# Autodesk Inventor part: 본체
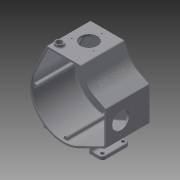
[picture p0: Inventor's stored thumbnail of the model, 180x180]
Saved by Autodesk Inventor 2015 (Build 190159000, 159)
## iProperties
Created: 2017-05
Part Number: 본체
Material: 알루미늄 6061
Document SubType Name: Modeling
Designer: mduedu
Density: 2.71 g/cm^3
Mass: 1345.72 g
Surface Area: 1824.08 cm^2
Volume: 496.576 cm^3
Appearance: 기본값
Author: mduedu
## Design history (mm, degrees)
sketch "스케치1"
  geometry: L1 (-71.801, 35.28)-(-40, 100); L2 (-40, 100)-(40, 100); L3 (40, 100)-(59.768, 59.768); L4 (59.768, 59.768)-(100, 40); L5 (100, 40)-(100, -40); L6 (100, -40)-(35.28, -71.801); A1 r 80 centre (0, 0) between (-71.801, 35.28) and (35.28, -71.801); 3 further points
  constraints: 12 end point, 4 tangent, 2 midpoint, 2 point on circle, 1 centre point, 1 coincident, 1 horizontal, 1 horizontal alignment, 1 perpendicular, 1 vertical alignment
  dimensions: "d0" = 160 diameter of A1; "d2" = 100 distance from line of L2 point (0, 0); "d3" = 100 distance from line of L5 point (0, 0); "d4" = 80 distance of L1.end L2.end; "d5" = 80 distance of L4.end L5.end
extrude "돌출1" new body sketch "스케치1" distance "d6" = 5; taper "d7" = 0 deg
fillet "모깎기1" dims "d8" = 50
sketch "스케치2"
  geometry: C1 r 22 at (0, 0); 1 further point
  constraints: 1 centre point, 1 coincident
  dimensions: "d9" = 44 diameter of C1
extrude "돌출2" join sketch "스케치2" distance "d10" = 22.5; taper "d11" = 0 deg
sketch "스케치3"
  geometry: C1 r 18.5 at (0, 0); 1 further point
  constraints: 1 centre point, 1 coincident
  dimensions: "d12" = 37 diameter of C1
extrude "돌출3" cut sketch "스케치3" distance "d13" = 9; taper "d14" = 0 deg
fillet "모깎기2" dims "d15" = 3
sketch "스케치4"
  geometry: L1 (35.28, -71.801)-(100, -40) reference; L2 (100, -40)-(100, 40) reference; L3 (100, 40)-(75.073, 52.248) reference; L4 (52.248, 75.073)-(40, 100) reference; L5 (40, 100)-(-40, 100) reference; L6 (-40, 100)-(-71.801, 35.28) reference; L7 (-36.886, 95)-(36.886, 95); L8 (36.886, 95)-(47.76, 72.868); L9 (72.868, 47.76)-(95, 36.886); L10 (95, 36.886)-(95, -36.886); L11 (95, -36.886)-(33.075, -67.313); L12 (-67.313, 33.075)-(-36.886, 95); C1 r 25 at (0, 0) reference; A1 r 50 centre (97.123, 97.123) between (52.248, 75.073) and (75.073, 52.248) reference; A2 r 80 centre (0, 0) between (-71.801, 35.28) and (35.28, -71.801) reference; A3 r 55 centre (97.123, 97.123) between (47.76, 72.868) and (72.868, 47.76); A4 r 75 centre (0, 0) between (-67.313, 33.075) and (33.075, -67.313); 1 further point
  constraints: 12 end point, 4 point on circle, 2 centre point, 7 other
  dimensions: "d16" = 5 distance between parallel lines of L7 L5
extrude "돌출4" join sketch "스케치4" distance "d17" = 100; taper "d18" = 0 deg
sketch "스케치5"
  geometry: L1 (80, 0)-(0, 0) reference; C1 r 20 at (40, -45); 2 further points
  constraints: 1 centre point, 1 midpoint, 1 vertical alignment
  dimensions: "d19" = 40 diameter of C1; "d21" = 45 distance from line of C1.centre L1
extrude "돌출5" cut sketch "스케치5" stored distance "d22" = 100; taper "d23" = 0 deg
sketch "스케치6"
  geometry: L1 (0, 0)-(0, -105) reference; L2 (80, -105)-(0, -105) reference; C1 r 9 at (14, -89); 1 further point
  constraints: 1 centre point
  dimensions: "d24" = 18 diameter of C1; "d26" = 14 distance from line of C1.centre L1; "d27" = 16 distance from line of C1.centre L2
extrude "돌출6" join sketch "스케치6" distance "d28" = 7; taper "d29" = 0 deg
hole "구멍1" diameter "d32" = 14; stored, may be unused: countersink angle "d36" = 90 deg, drill point angle "d38" = 118 deg; dims "d33" = 6, "d34" = 4, "d35" = 2, "d37" = 8, "d39" = 10, "d40" = 10
sketch "스케치7"
  geometry: L1 (-105, 0)-(-105, 80) reference; L2 (0, 0)-(0, 80) reference; C1 r 20 at (-70, 40); 2 further points
  constraints: 1 centre point, 1 horizontal alignment, 1 midpoint
  dimensions: "d41" = 40 diameter of C1; "d42" = 35 distance from line of C1.centre L1
extrude "돌출7" cut sketch "스케치7" stored distance "d43" = 7; taper "d44" = 0 deg
node "작업 평면1"
sketch "스케치8"
  geometry: L1 (47.76, 72.868)-(36.886, 95) reference; L2 (36.886, 95)-(-36.886, 95) reference; L3 (-36.886, 95)-(-67.313, 33.075) reference; L4 (33.075, -67.313)-(95, -36.886) reference; L5 (95, -36.886)-(95, 36.886) reference; L6 (95, 36.886)-(72.868, 47.76) reference; L7 (95, 36.886)-(95, -36.886) reference; L8 (-36.886, 95)-(36.886, 95) reference; L9 (36.886, 95)-(47.76, 72.868) reference; L10 (-71, 4)-(-74.893, 4); L11 (-71, -4)-(-74.893, -4); L12 (-4, -71)-(-4, -74.893); L13 (4, -71)-(4, -74.893); L14 (30.394, 91)-(30.394, 95); L15 (34.394, 87)-(40.817, 87); L16 (30.394, 95)-(36.886, 95); L17 (36.886, 95)-(37.984, 92.764); L18 (91, 30.394)-(95, 30.394); L19 (87, 34.394)-(87, 40.817); L20 (87, 40.817)-(95, 36.886); L21 (95, 36.886)-(95, 30.394); C1 r 25 at (0, 0) reference; A1 r 75 centre (0, 0) between (-67.313, 33.075) and (33.075, -67.313) reference; A2 r 55 centre (97.123, 97.123) between (47.76, 72.868) and (72.868, 47.76) reference; A3 r 4 centre (-71, 0) between (-71, 4) and (-71, -4); A4 r 4 centre (0, -71) between (-4, -71) and (4, -71); A5 r 4 centre (34.394, 91) between (30.394, 91) and (34.394, 87); A6 r 75 centre (0, 0) between (-67.313, 33.075) and (33.075, -67.313) reference; A7 r 4 centre (91, 34.394) between (91, 30.394) and (87, 34.394); 1 further point
  constraints: 24 end point, 17 point on circle, 14 tangent, 5 point on line, 4 centre point, 3 equal radius, 3 perpendicular, 3 vertical, 2 collinear, 2 horizontal, 1 horizontal alignment, 1 parallel, 1 vertical alignment
  dimensions: "d46" = 8 diameter of A3
extrude "돌출8" join sketch "스케치8" stored distance "d49" = 7; taper "d50" = 0 deg
node "작업 평면2"
sketch "스케치9"
  geometry: L1 (71.801, 0)-(71.801, 105) reference; L2 (71.801, 0)-(-35.28, 0) reference; L3 (-35.28, 0)-(-35.28, 105) reference; L4 (71.801, 105)-(-35.28, 105) reference; L5 (40, 0)-(40, 105) reference; L6 (71.801, 52.5)-(-35.28, 52.5); L7 (71.801, 20)-(40, 20); L8 (40, 20)-(40, 85); L9 (40, 85)-(71.801, 85); L10 (71.801, 85)-(71.801, 20); 1 further point
  constraints: 10 end point, 2 midpoint, 2 parallel, 2 point on line, 1 horizontal, 1 perpendicular, 1 other
  dimensions: "d52" = 20 distance between parallel lines of L7 L2
extrude "돌출9" join sketch "스케치9" distance "d53" = 8; taper "d54" = 0 deg
fillet "모깎기3" dims "d55" = 8
sketch "스케치10"
  geometry: C1 r 4 at (-63.801, -28); C2 r 4 at (-63.801, -77); A1 r 8 centre (-63.801, -28) between (-63.801, -20) and (-71.801, -28) reference; A2 r 8 centre (-63.801, -77) between (-71.801, -77) and (-63.801, -85) reference; 1 further point
  constraints: 2 centre point, 2 coincident, 1 equal radius
  dimensions: "d56" = 8 diameter of C1
extrude "돌출10" cut sketch "스케치10" stored distance "d57" = 50.5; taper "d58" = 0 deg
sketch "스케치11"
  geometry: L1 (-63.801, -20)-(-40, -20) reference; L2 (-40, -20)-(-40, -85) reference; L3 (-40, -85)-(-63.801, -85) reference; L4 (-71.801, -77)-(-71.801, -28) reference; L5 (71.801, -77)-(71.801, -28) reference; L6 (40, -85)-(63.801, -85) reference; L7 (40, -20)-(40, -85) reference; L8 (63.801, -20)-(40, -20) reference; L9 (-40, -85)-(-48, -85); L10 (-48, -85)-(-48, -20); L11 (-48, -20)-(-40, -20); L12 (-40, -20)-(-40, -85); L13 (40, -85)-(48, -85); L14 (48, -85)-(48, -20); L15 (48, -20)-(40, -20); L16 (40, -20)-(40, -85); C1 r 4 at (-63.801, -28) reference; C2 r 4 at (-63.801, -77) reference; C3 r 4 at (63.801, -28) reference; C4 r 4 at (63.801, -77) reference; A1 r 8 centre (-63.801, -28) between (-63.801, -20) and (-71.801, -28) reference; A2 r 8 centre (-63.801, -77) between (-71.801, -77) and (-63.801, -85) reference; A3 r 8 centre (63.801, -28) between (71.801, -28) and (63.801, -20) reference; A4 r 8 centre (63.801, -77) between (63.801, -85) and (71.801, -77) reference; 1 further point
  constraints: 16 end point, 4 parallel, 2 horizontal, 2 perpendicular, 2 point on line
  dimensions: "d59" = 8 distance of L10.end L11.end; "d61" = 8 distance of L14.end L15.end
extrude "돌출11" join sketch "스케치11" stored distance "d62" = 5; taper "d63" = 0 deg
fillet "모깎기4" dims "d64" = 5
fillet "모깎기5" dims "d65" = 2
fillet "모깎기6" dims "d66" = 2
fillet "모깎기8" dims "d68" = 2
fillet "모깎기9" dims "d70" = 3, "d101" = 1
fillet "모깎기10" dims "d71" = 3
fillet "모깎기11" dims "d72" = 3
fillet "모깎기12" dims "d73" = 3
fillet "모깎기13" dims "d76" = 3
chamfer "모따기1" distance "d77" = 0.5; stored, may be unused: second distance "d78" = 2, angle "d79" = 45 deg
chamfer "모따기2" distance "d87" = 1; stored, may be unused: second distance "d88" = 2, angle "d89" = 45 deg
chamfer "모따기3" distance "d90" = 1; stored, may be unused: second distance "d91" = 2, angle "d92" = 45 deg
sketch "스케치14"
  geometry: 3 further points
  constraints: 3 other
hole "구멍2" sketch "스케치14" at (-55.375, -40), (-3.414, -40), (-29.394, -85) diameter "d93" = 2.459; stored, may be unused: countersink angle "d97" = 90 deg, drill point angle "d99" = 0 deg; dims "d94" = 6, "d95" = 4, "d96" = 2, "d98" = 8
sketch "스케치15"
  geometry: 3 further points
  constraints: 3 other
hole "구멍4" sketch "스케치15" at (-55.981, -14.394), (-4.019, -14.394), (-30, -59.394) diameter "d102" = 2.459; stored, may be unused: countersink angle "d106" = 90 deg, drill point angle "d108" = 0 deg; dims "d103" = 6, "d104" = 4, "d105" = 2, "d107" = 8
sketch "스케치16"
  geometry: 4 further points
  constraints: 4 other
hole "구멍6" sketch "스케치16" at (0, -71), (91, 34.394), (34.394, 91), (-71, 0) diameter "d109" = 2.459; stored, may be unused: countersink angle "d113" = 90 deg, drill point angle "d115" = 120 deg; dims "d110" = 8.5, "d111" = 4, "d112" = 2, "d114" = 10
node "작업 평면4"
sketch "스케치17"
  geometry: 2 further points
  constraints: 1 horizontal alignment, 1 other
  dimensions: "d116" = 52.5 distance of point (0, 16.14) point (52.5, 16.14)
feature "엠보싱2" sketch "스케치17" dims "d117" = 0.5, "d118" = 0
node "솔리드1"
mirror "대칭1"
node "투영된 루프1"
node "투영된 루프2"
node "투영된 루프3"
node "투영된 루프4"
node "투영된 루프5"
other parameters: "d45" = 95
